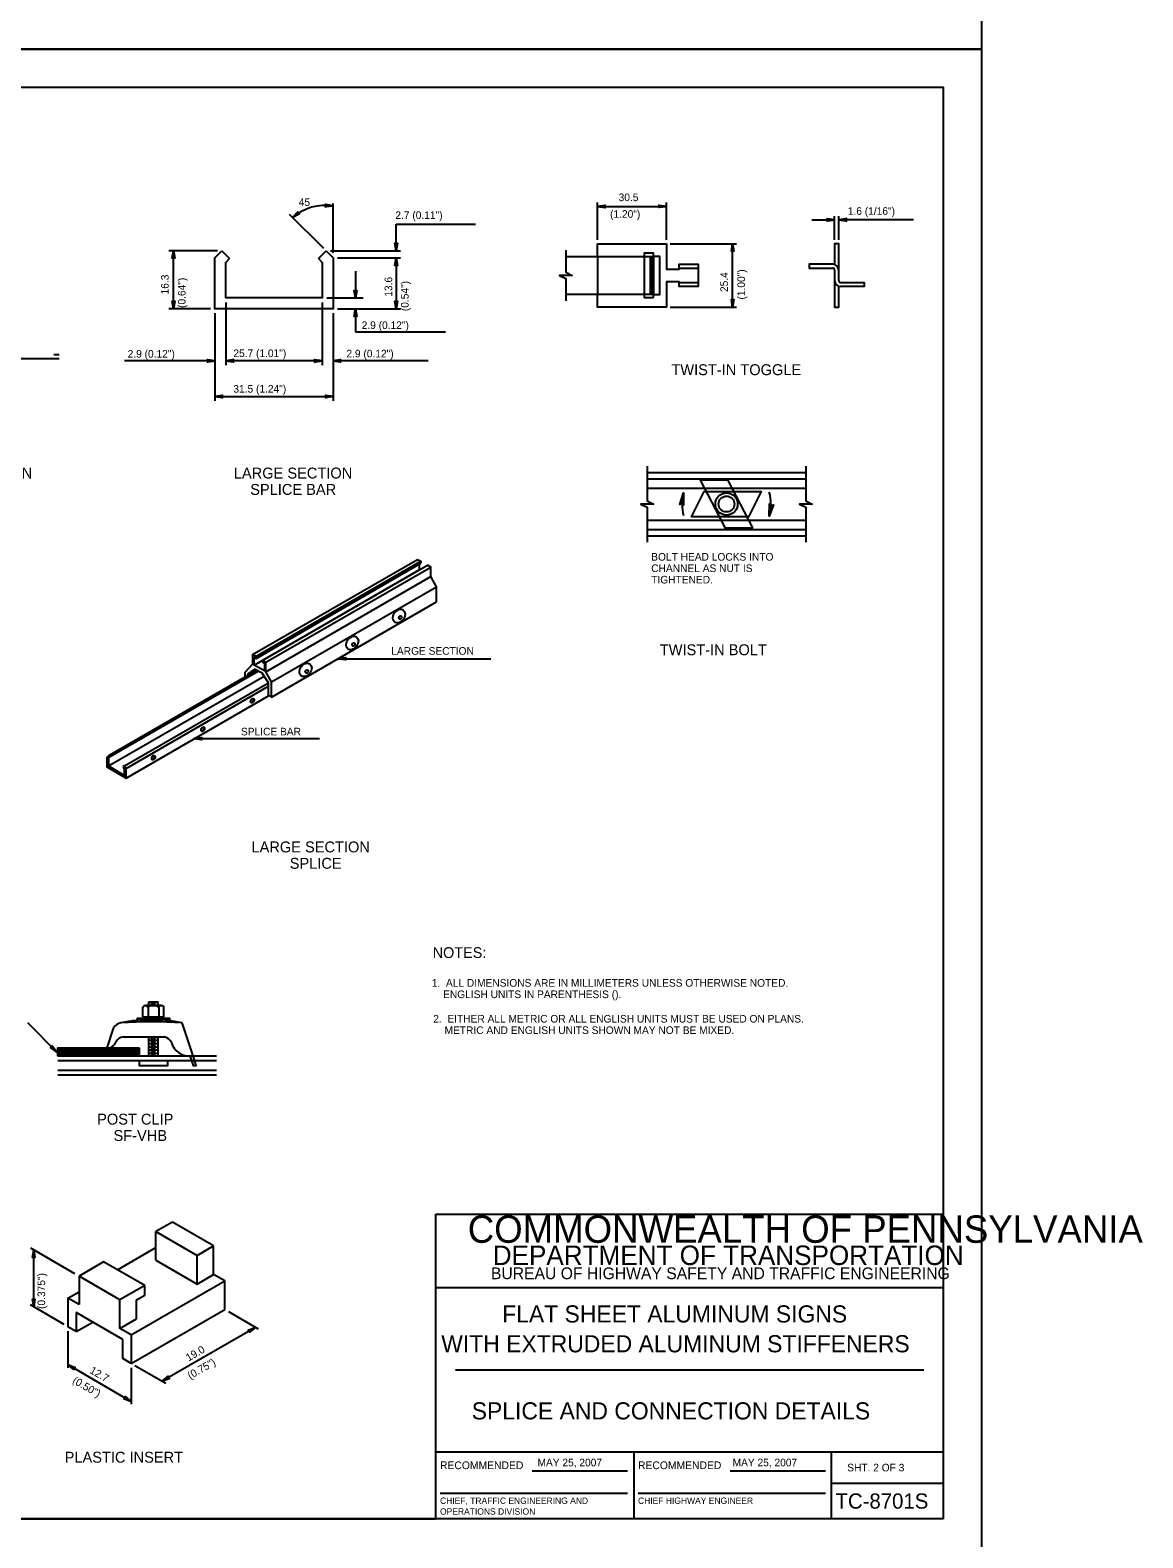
# Model space of a CAD drawing. Extents: x 650495 to 651400, y 297864 to 299646.
# Drawn here: x 650962 to 651400, y 298465 to 299059 of the extents above; entities that cross this region are included whole.
import ezdxf

# ---------------------------------------------------------------- set-up
doc = ezdxf.new("R2010")
doc.units = 0
for name, color, linetype in [('1', 7, 'Continuous'), ('2', 7, 'Continuous'), ('3', 7, 'Continuous'), ('PLT-BNDY', 7, 'Continuous')]:
    doc.layers.add(name, color=color, linetype=linetype)

# ---------------------------------------------------------------- blocks, each defined once
blk = doc.blocks.new('RARROW')
at = {"layer": '3'}
blk.add_lwpolyline([(-2.2695, 0.285), (-2.184875, 0.12075), (0, 0), (-2.2695, 0.285), (-2.38575, 0.384625), (0, 0), (-2.183125, -0.108), (-2.262875, -0.2705), (0, 0), (-2.38575, -0.379125), (-2.262875, -0.2705)], dxfattribs=at)

msp = doc.modelspace()

# ---------------------------------------------------------------- linework, layer by layer
at = {"layer": '1'}
for p, q in [((650535.31, 299036.63), (651321.31, 299036.63)), ((651321.31, 298472.63), (651321.31, 299036.63)), ((651121.31, 298472.63), (651121.31, 298592.63)), ((651121.31, 298592.63), (651321.31, 298592.63)), ((651321.31, 298563.63), (651121.31, 298563.63)), ((651129.06, 298531.31), (651313.56, 298531.31)), ((651121.31, 298499), (651321.31, 298499)), ((651199.31, 298499), (651199.31, 298472.63)), ((651277.19, 298472.63), (651277.19, 298499)), ((651159.24, 298491.57), (651196.87, 298491.57)), ((651237.24, 298491.57), (651274.87, 298491.57)), ((651277.19, 298486.63), (651321.31, 298486.63)), ((651122.99, 298482.68), (651196.87, 298482.68)), ((651200.99, 298482.68), (651274.87, 298482.68)), ((651321.31, 298472.63), (650535.31, 298472.63)), ((650535.31, 298472.63), (651121.31, 298472.63))]:
    msp.add_line(p, q, dxfattribs=at)
at = {"layer": '2'}
for p, q in [((651080.83, 298971.36), (651080.83, 298990.86)), ((651185.07, 298976.5), (651185.07, 298991.19)), ((651212.14, 298976.5), (651212.14, 298991.19)), ((651077.21, 298973.11), (651063.71, 298986.49)), ((651185.07, 298989.69), (651212.14, 298989.69)), ((651269.44, 298984.38), (651278.44, 298984.38)), ((651278.44, 298976.5), (651278.44, 298985.88)), ((651280.06, 298976.5), (651280.06, 298985.88)), ((651309.47, 298984.38), (651280.06, 298984.38)), ((651105.71, 298972.23), (651105.71, 298982.74)), ((651105.71, 298982.74), (651136.92, 298982.74)), ((651035.33, 298972.23), (651016.21, 298972.23)), ((651017.96, 298949.36), (651017.96, 298972.23)), ((651037.08, 298972.23), (651040.08, 298969.11)), ((651075.08, 298969.11), (651078.08, 298972.23)), ((651079.83, 298972.23), (651107.46, 298972.23)), ((651213.64, 298975), (651239.76, 298975)), ((651238.26, 298950), (651238.26, 298975)), ((651082.58, 298969.36), (651107.46, 298969.36)), ((651105.71, 298969.36), (651105.71, 298949.36)), ((651185.07, 298970), (651185.07, 298955)), ((651203.39, 298970), (651203.39, 298955)), ((651205.76, 298970), (651205.76, 298955)), ((651206.51, 298970), (651206.51, 298955)), ((651089.65, 298964.11), (651089.65, 298953.61)), ((651217.14, 298965.38), (651224.64, 298965.38)), ((651278.44, 298964.63), (651278.44, 298960.5)), ((651217.14, 298959.75), (651224.64, 298959.75)), ((651032.58, 298949.36), (651016.21, 298949.36)), ((651038.58, 298951.86), (651038.58, 298927.09)), ((651076.58, 298951.86), (651076.58, 298927.09)), ((651078.33, 298953.61), (651092.72, 298953.61)), ((651082.58, 298949.36), (651096.83, 298949.36)), ((651082.58, 298949.36), (651107.46, 298949.36)), ((651089.65, 298949.36), (651089.65, 298940.23)), ((651213.64, 298950), (651239.76, 298950)), ((651034.33, 298947.61), (651034.33, 298927.09)), ((651034.33, 298947.61), (651034.33, 298913.08)), ((651080.83, 298947.61), (651080.83, 298927.09)), ((651080.83, 298947.61), (651080.83, 298913.08)), ((651089.65, 298940.23), (651125.18, 298940.23)), ((650970.9, 298931.39), (650972.89, 298931.39)), ((650888.65, 298929.7), (650973, 298929.7)), ((651034.33, 298928.84), (650998.63, 298928.84)), ((651076.58, 298928.84), (651038.58, 298928.84)), ((651087.08, 298928.84), (651080.83, 298928.84)), ((651118.32, 298928.84), (651080.83, 298928.84)), ((651034.33, 298914.83), (651080.83, 298914.83)), ((651204.56, 298884.88), (651267.06, 298884.88)), ((651204.56, 298882.38), (651267.06, 298882.38)), ((651204.56, 298878.63), (651267.06, 298878.63)), ((651204.56, 298866.13), (651267.06, 298866.13)), ((651204.56, 298862.38), (651267.06, 298862.38)), ((651204.56, 298859.88), (651267.06, 298859.88)), ((651049.15, 298813.11), (651114.15, 298850.61)), ((651049.78, 298811.99), (651114.78, 298849.49)), ((651050.53, 298812.36), (651115.4, 298849.86)), ((651050.53, 298811.61), (651115.4, 298849.11)), ((651053.15, 298810.86), (651118.03, 298848.36)), ((651054.4, 298810.11), (651119.4, 298847.61)), ((651049.78, 298808.99), (651114.78, 298846.49)), ((651054.4, 298806.36), (651119.4, 298843.86)), ((651056.65, 298802.36), (651121.65, 298839.86)), ((651056.65, 298796.36), (651121.65, 298833.86)), ((650992.65, 298773.49), (651050.65, 298806.99)), ((650993.03, 298772.99), (651051.28, 298806.61)), ((651082.9, 298811.49), (651142.95, 298811.49)), ((650992.4, 298769.24), (651053.65, 298804.61)), ((650998.65, 298769.24), (651055.4, 298801.99)), ((650999.28, 298768.24), (651055.4, 298800.61)), ((650999.28, 298764.49), (651055.4, 298796.86)), ((651026.15, 298779.99), (651075.57, 298779.99)), ((650993.03, 298772.99), (650992.65, 298773.49)), ((650998.65, 298769.24), (650998.15, 298768.99)), ((651008.22, 298676.27), (651011.97, 298676.27)), ((651008.22, 298674.89), (651008.22, 298676.27)), ((651008.35, 298676.14), (651011.72, 298676.14)), ((651009.1, 298675.52), (651010.85, 298675.52)), ((651011.97, 298674.89), (651011.97, 298676.27)), ((651005.85, 298670.39), (651005.85, 298674.14)), ((651005.85, 298670.39), (651014.22, 298670.39)), ((651006.22, 298670.39), (651006.22, 298670.14)), ((651006.22, 298670.14), (651013.97, 298670.14)), ((651013.1, 298674.89), (651006.97, 298674.89)), ((651007.97, 298674.02), (651007.97, 298670.39)), ((651012.22, 298674.02), (651012.22, 298670.39)), ((651013.97, 298670.39), (651013.97, 298670.14)), ((651014.22, 298670.39), (651014.22, 298674.14)), ((650971.97, 298656.52), (650960.54, 298668.02)), ((650991.85, 298658.14), (650994.47, 298666.14)), ((651025.72, 298655.02), (651021.35, 298668.02)), ((650998.22, 298662.52), (651014.47, 298662.52)), ((651008.22, 298655.02), (651008.22, 298662.52)), ((651008.35, 298662.39), (651011.72, 298662.39)), ((651008.35, 298661.14), (651011.72, 298661.14)), ((651008.35, 298659.89), (651011.72, 298659.89)), ((651008.35, 298658.64), (651011.72, 298658.64)), ((651008.35, 298657.39), (651011.72, 298657.39)), ((651009.1, 298661.77), (651010.85, 298661.77)), ((651009.1, 298660.52), (651010.85, 298660.52)), ((651009.1, 298659.27), (651010.85, 298659.27)), ((651009.1, 298658.02), (651010.85, 298658.02)), ((651011.97, 298655.02), (651011.97, 298662.52)), ((650972.47, 298655.02), (651034.97, 298655.02)), ((650972.47, 298653.14), (651034.97, 298653.14)), ((651008.35, 298656.14), (651011.72, 298656.14)), ((651009.1, 298656.77), (651010.85, 298656.77)), ((651009.1, 298655.52), (651010.85, 298655.52)), ((651015.72, 298653.14), (651015.72, 298653.14)), ((651024.47, 298655.02), (651024.47, 298655.02)), ((650972.47, 298649.39), (651034.97, 298649.39)), ((650972.47, 298647.52), (651034.97, 298647.52)), ((651017.53, 298589.51), (651011.03, 298585.76)), ((651033.78, 298580.13), (651017.53, 298589.51)), ((651011.03, 298585.76), (651027.28, 298576.38)), ((651011.03, 298574.51), (651011.03, 298585.76)), ((651027.28, 298576.38), (651033.78, 298580.13)), ((651033.78, 298568.88), (651033.78, 298580.13)), ((650979.16, 298569.13), (650961.78, 298579.28)), ((650962.91, 298556.13), (650962.91, 298578.63)), ((650995.91, 298570.76), (651011.03, 298579.51)), ((651011.03, 298574.51), (651027.28, 298565.13)), ((651027.28, 298565.13), (651027.28, 298576.38)), ((650990.41, 298573.88), (650980.78, 298568.26)), ((650996.91, 298558.88), (650980.78, 298568.26)), ((650980.78, 298568.26), (650980.78, 298557.01)), ((651006.66, 298564.51), (650990.41, 298573.88)), ((651027.28, 298565.13), (651033.78, 298568.88)), ((651038.16, 298566.38), (651033.78, 298568.88)), ((651006.66, 298564.51), (650996.91, 298558.88)), ((651001.28, 298545.13), (651038.16, 298566.38)), ((651006.66, 298560.76), (651006.66, 298564.51)), ((651038.16, 298555.13), (651038.16, 298566.38)), ((650974.91, 298549.13), (650961.59, 298556.9)), ((650976.41, 298559.51), (650980.78, 298562.01)), ((650976.41, 298559.51), (650976.41, 298548.26)), ((650980.78, 298557.01), (650976.41, 298559.51)), ((650996.91, 298547.63), (650996.91, 298558.88)), ((651003.41, 298558.88), (651006.66, 298560.76)), ((651003.41, 298551.38), (651003.41, 298558.88)), ((650998.03, 298543.26), (650979.66, 298553.88)), ((650979.66, 298553.88), (650979.66, 298546.38)), ((650996.91, 298547.63), (651003.41, 298551.38)), ((651001.28, 298533.88), (651038.16, 298555.13)), ((651039.66, 298554.26), (651051.28, 298547.49)), ((650979.66, 298546.38), (650976.41, 298548.26)), ((650976.41, 298546.51), (650976.41, 298532.13)), ((650979.66, 298546.38), (650986.16, 298550.13)), ((651001.28, 298545.13), (650996.91, 298547.63)), ((651001.28, 298545.13), (651001.28, 298533.88)), ((651050.3, 298548.06), (651013.58, 298526.84)), ((650998.03, 298535.76), (650998.03, 298543.26)), ((650976.41, 298533.36), (651001.28, 298518.84)), ((651001.28, 298533.88), (650998.03, 298535.76)), ((651002.78, 298533.01), (651014.99, 298526.03)), ((651001.28, 298532.13), (651001.28, 298517.76))]:
    msp.add_line(p, q, dxfattribs=at)
for points in [[(651078.08, 298972.23), (651080.83, 298969.36), (651080.83, 298949.36), (651034.33, 298949.36), (651034.33, 298969.36), (651037.08, 298972.23)], [(651172.57, 298972.5), (651172.57, 298963.75), (651175.07, 298962.5), (651170.07, 298962.5), (651172.57, 298961.25), (651172.57, 298952.5)], [(651185.07, 298970), (651185.07, 298975), (651212.14, 298975), (651212.14, 298965), (651217.14, 298965), (651217.14, 298966.88), (651224.64, 298966.88), (651224.64, 298958.13), (651217.14, 298958.13), (651217.14, 298960), (651212.14, 298960), (651212.14, 298950), (651185.07, 298950), (651185.07, 298955)], [(651280.06, 298960.5), (651280.06, 298975), (651278.44, 298975), (651278.44, 298966.78)], [(651075.08, 298969.11), (651076.58, 298967.61), (651076.58, 298953.61), (651038.58, 298953.61), (651038.58, 298967.61), (651040.08, 298969.11)], [(651172.57, 298970), (651207.14, 298970), (651207.14, 298955), (651172.57, 298955)], [(651277.76, 298966.88), (651268.44, 298966.88), (651268.44, 298965.38), (651277.69, 298965.38)], [(651278.44, 298964.63), (651278.44, 298950), (651280.06, 298950), (651280.06, 298958.23)], [(651280.81, 298959.75), (651290.06, 298959.75), (651290.06, 298958.13), (651280.74, 298958.13)], [(651204.56, 298887.38), (651204.56, 298873.63), (651207.06, 298872.38), (651202.06, 298872.38), (651204.56, 298871.13), (651204.56, 298857.38)], [(651267.06, 298887.38), (651267.06, 298873.63), (651269.56, 298872.38), (651264.56, 298872.38), (651267.06, 298871.13), (651267.06, 298857.38)], [(651235.81, 298877.38), (651249.56, 298877.38), (651244.56, 298867.38), (651222.06, 298867.38), (651227.06, 298877.38), (651235.81, 298877.38)], [(651231.69, 298870.25), (651225.56, 298881.88), (651236.19, 298882), (651246.06, 298863), (651235.44, 298862.88), (651231.69, 298870.25)], [(651217.69, 298872.5), (651217.94, 298872.63), (651218.94, 298876.88), (651217.69, 298872.5), (651217.44, 298872.25), (651218.94, 298876.88), (651218.44, 298872.5), (651218.69, 298872.38), (651218.94, 298876.88), (651218.94, 298872), (651218.69, 298872.38)], [(651254.06, 298872), (651253.69, 298871.88), (651252.69, 298867.63), (651254.06, 298872), (651254.31, 298872.13), (651252.69, 298867.63), (651253.19, 298872), (651252.94, 298872.13), (651252.69, 298867.63), (651252.81, 298872.5), (651252.94, 298872.13)], [(651114.15, 298850.61), (651115.4, 298849.86), (651115.4, 298849.11)], [(651114.78, 298848.74), (651114.78, 298846.49)], [(651121.65, 298833.86), (651121.65, 298839.86), (651119.4, 298843.86), (651119.4, 298847.61), (651118.03, 298848.36)], [(651055.4, 298797.11), (651056.65, 298796.36), (651056.65, 298802.36), (651054.4, 298806.36), (651054.4, 298810.11), (651053.15, 298810.86), (651053.15, 298810.11), (651053.78, 298809.74), (651053.78, 298806.74), (651049.78, 298808.99), (651049.78, 298811.99), (651050.53, 298811.61), (651050.53, 298812.36), (651049.15, 298813.11), (651049.15, 298809.36), (651046.03, 298806.11), (651046.03, 298804.24)], [(651055.4, 298797.11), (651055.4, 298801.99), (651052.9, 298805.74), (651049.9, 298807.36), (651047.28, 298805.49), (651047.28, 298804.99)], [(650992.65, 298773.49), (650991.78, 298772.61), (650991.78, 298768.86), (650999.28, 298764.49), (650999.28, 298768.24), (650998.65, 298769.24)], [(650993.03, 298772.99), (650992.4, 298772.36), (650992.4, 298769.24), (650998.65, 298765.49), (650998.65, 298767.99), (650998.15, 298768.99)], [(650972.72, 298657.52), (651003.97, 298657.52), (651003.97, 298655.64), (650972.72, 298655.39), (650972.72, 298657.14), (651003.47, 298657.14), (651003.6, 298656.14), (650973.35, 298655.64), (650973.47, 298656.64), (651002.72, 298656.64), (651002.72, 298656.52), (650973.6, 298656.14)], [(651004.47, 298653.14), (651004.47, 298651.27), (651015.72, 298651.27), (651015.72, 298653.14)], [(651024.47, 298655.02), (651025.72, 298651.27), (651026.97, 298651.27), (651025.72, 298655.02)]]:
    msp.add_lwpolyline(points, dxfattribs=at)
for points in [[(651207.14, 298970), (651207.14, 298971.25), (651203.39, 298971.25), (651203.39, 298970)], [(651207.14, 298970), (651207.14, 298955), (651209.64, 298955), (651209.64, 298970)], [(651207.14, 298953.75), (651207.14, 298955), (651203.39, 298955), (651203.39, 298953.75)], [(651003.85, 298669.27), (651003.85, 298669.89), (651016.35, 298669.89), (651016.35, 298669.27)], [(651004.47, 298658.14), (651004.47, 298655.02), (650972.47, 298655.02), (650972.47, 298658.14)]]:
    msp.add_lwpolyline(points, close=True, dxfattribs=at)
for radius in [4.38, 3.12]:
    msp.add_circle((651235.85, 298872.42), radius, dxfattribs=at)
for centre, radius, start, end in [((651077.83, 298969.94), 20.14, 81.42065, 130.10106), ((651277.76, 298964.58), 2.3, 0, 90), ((651277.69, 298964.63), 0.75, 0, 90), ((651280.74, 298960.43), 2.3, 180, 270), ((651280.81, 298960.5), 0.75, 180, 270), ((651235.85, 298872.42), 17.49, 344.07384, 15.48813), ((651235.85, 298872.42), 17.49, 165.2574, 194.94011), ((651009.31, 298612.21), 57.12, 77.80349, 102.1965), ((651007.03, 298674.76), 0.113, 90, 180), ((651013.1, 298674.76), 0.113, 0, 90), ((650998.31, 298663.56), 4.6, 103.47229, 145.70272), ((651009.31, 298493.5), 174.95, 86.04462, 93.95539), ((650991.89, 298661.49), 3.48, 282.55259, 342.47234), ((650998.61, 298658.69), 3.82, 95.78592, 152.80494), ((651013.51, 298658.45), 4.15, 26.88629, 76.60858), ((651024.12, 298662.12), 7.13, 194.52183, 272.8108)]:
    msp.add_arc(centre, radius, start, end, dxfattribs=at)
for centre, major_axis, ratio in [((651106.81, 298828.32), (1.7, 2.34), 0.738176), ((651107.29, 298827.73), (0.425, 0.585), 0.738176), ((651088.41, 298817.69), (1.7, 2.34), 0.738176), ((651088.89, 298817.11), (0.425, 0.585), 0.738176), ((651070, 298807.07), (1.7, 2.34), 0.738176), ((651070.48, 298806.48), (0.425, 0.585), 0.738176), ((651049.05, 298795.01), (0.443, 0.822), 0.636755), ((651029.56, 298783.76), (0.443, 0.822), 0.636755), ((651010.07, 298772.51), (0.443, 0.822), 0.636755)]:
    msp.add_ellipse(centre, major_axis=major_axis, ratio=ratio, dxfattribs=at)
for centre, major_axis, ratio, start_param, end_param in [((651048.88, 298795.1), (0.443, 0.822), 0.636755, 3.280378, 6.105665), ((651029.4, 298783.85), (0.443, 0.822), 0.636755, 3.280378, 6.105665), ((651009.91, 298772.6), (0.443, 0.822), 0.636755, 3.280378, 6.105665), ((651006.91, 298674.04), (1.03, 0.01), 0.679853, 0, 3.035161), ((651010.06, 298674.06), (-2.12, -0.01), 0.335964, 3.141593, 6.283185), ((651013.21, 298674.06), (-1.03, 0.01), 0.679853, 3.248025, 6.283185)]:
    msp.add_ellipse(centre, major_axis=major_axis, ratio=ratio, start_param=start_param, end_param=end_param, dxfattribs=at)
at = {"layer": 'PLT-BNDY'}
for points in [[(650495.31, 299645.63), (651336.31, 299645.63), (651336.31, 299051.63), (650495.31, 299051.63)], [(650495.31, 299051.63), (651336.31, 299051.63), (651336.31, 298457.63), (650495.31, 298457.63)]]:
    msp.add_lwpolyline(points, close=True, dxfattribs=at)

# ---------------------------------------------------------------- block references
at = {"layer": '2'}
for p, xscale, yscale, rotation in [((651080.83, 298989.86), 1.257434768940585, 1.3092961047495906, -4.1307990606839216), ((651185.07, 298989.69), 1.2574347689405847, 1.3092961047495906, 180), ((651064.86, 298985.35), 1.2574347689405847, 1.3092961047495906, -143.18293648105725), ((651280.06, 298984.38), 1.2574347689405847, 1.3092961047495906, 180), ((651017.96, 298972.23), 1.2574347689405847, 1.3092961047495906, 89.99999999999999), ((651105.71, 298972.23), 1.2574347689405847, 1.3092961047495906, -90.00000000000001), ((651238.26, 298975), 1.2574347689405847, 1.3092961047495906, 89.99999999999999), ((651105.71, 298969.36), 1.2574347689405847, 1.3092961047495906, 89.99999999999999), ((651089.65, 298953.61), 1.2574347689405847, 1.3092961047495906, -90.00000000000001), ((651017.96, 298949.36), 1.2574347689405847, 1.3092961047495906, -90.00000000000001), ((651089.65, 298949.36), 1.2574347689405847, 1.3092961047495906, 89.99999999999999), ((651105.71, 298949.36), 1.2574347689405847, 1.3092961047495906, -90.00000000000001), ((651238.26, 298950), 1.2574347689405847, 1.3092961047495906, -90.00000000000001), ((651038.58, 298928.84), 1.2574347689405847, 1.3092961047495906, 180), ((651080.83, 298928.84), 1.2574347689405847, 1.3092961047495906, 180), ((651034.33, 298914.83), 1.2574347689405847, 1.3092961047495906, 180), ((651082.9, 298811.49), 1.2574347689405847, 1.3092961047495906, 180), ((651026.15, 298779.99), 1.2574347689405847, 1.3092961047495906, 180), ((650971.97, 298656.52), 1.2574347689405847, 1.3092961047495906, -44.8426609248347), ((650971.97, 298656.52), 0.0018861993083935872, 0.001963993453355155, -46.50743575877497), ((650962.91, 298578.63), 1.2574347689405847, 1.3092961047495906, 89.99999999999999), ((650962.91, 298556.13), 1.2574347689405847, 1.3092961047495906, -90.00000000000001), ((651050.3, 298548.06), 1.2574347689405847, 1.3092961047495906, 30.434578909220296), ((650976.41, 298533.35), 1.2574347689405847, 1.3092961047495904, 149.64469446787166), ((651013.58, 298526.84), 1.2574347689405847, 1.3092961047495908, -149.86157797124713), ((651001.28, 298518.84), 1.2574347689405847, 1.3092961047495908, -30.0868603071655)]:
    msp.add_blockref('RARROW', p, dxfattribs=dict(at, xscale=xscale, yscale=yscale, rotation=rotation))
at = {"layer": '2', "xscale": 1.2574347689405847, "yscale": 1.3092961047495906}
for p in [(651212.14, 298989.69), (651278.44, 298984.38), (651034.33, 298928.84), (651076.58, 298928.84), (651080.83, 298914.83)]:
    msp.add_blockref('RARROW', p, dxfattribs=at)

# ---------------------------------------------------------------- texts
at = {"layer": '1'}
for s, height, p in [('COMMONWEALTH OF PENNSYLVANIA', 10.7828, (651133.9, 298581.36)), ('DEPARTMENT OF TRANSPORTATION', 7.6837, (651143.76, 298572.61)), ('BUREAU OF HIGHWAY SAFETY AND TRAFFIC ENGINEERING', 4.6253, (651143.04, 298567.04)), ('FLAT SHEET ALUMINUM SIGNS', 6.75, (651147.47, 298549.97)), ('WITH EXTRUDED ALUMINUM STIFFENERS', 6.75, (651123.47, 298538.22)), ('SPLICE AND CONNECTION DETAILS', 6.75, (651135.47, 298511.78)), ('RECOMMENDED', 3.048, (651122.99, 298492.2)), ('RECOMMENDED', 3.048, (651200.99, 298492.2)), ('SHT. 2 OF 3', 3, (651283.4, 298491.31)), ('CHIEF, TRAFFIC ENGINEERING AND', 2.5, (651122.99, 298478.51)), ('CHIEF HIGHWAY ENGINEER', 2.5, (651200.99, 298478.51)), ('TC-8701S', 6, (651278.79, 298476.63)), ('OPERATIONS DIVISION', 2.5, (651122.99, 298474.26))]:
    msp.add_text(s, height=height, dxfattribs=at).set_placement(p)
at = {"layer": '2'}
for s, height, p in [('45', 2.999, (651067.33, 298989.86)), ('30.5', 3, (651193.34, 298991.76)), ('2.7 (0.11")', 3, (651105.39, 298984.74)), ('(1.20")', 3, (651189.98, 298985.2)), ('1.6 (1/16")', 3, (651283.63, 298986.37)), ('2.9 (0.12")', 3, (651092.12, 298941.39)), ('2.9 (0.12")', 3, (650999.92, 298930.1)), ('25.7 (1.01")', 3, (651041.58, 298930.34)), ('2.9 (0.12")', 3, (651086.12, 298930.2)), ('TWIST-IN TOGGLE', 4.3, (651214.15, 298923.2)), ('31.5 (1.24")', 3, (651041.57, 298916.32)), ('SINGLE LARGE SECTION', 4.3, (650892.99, 298882.48)), ('LARGE SECTION', 4.3, (651041.76, 298882.48)), ('SPLICE BAR', 4.3, (651048.21, 298876.03)), ('CHANNEL AS NUT IS', 3, (651206.19, 298845.63)), ('BOLT HEAD LOCKS INTO', 3, (651206.19, 298850.13)), ('TIGHTENED.', 3, (651206.19, 298841.13)), ('LARGE SECTION', 3, (651103.77, 298813.05)), ('TWIST-IN BOLT', 4.3, (651209.57, 298812.86)), ('SPLICE BAR', 3, (651044.57, 298781.27)), ('LARGE SECTION', 4.3, (651048.71, 298735.18)), ('SPLICE', 4.3, (651063.78, 298728.73)), ('NOTES:', 4.25, (651120.08, 298693.58)), ('1.  ALL DIMENSIONS ARE IN MILLIMETERS UNLESS OTHERWISE NOTED.', 3, (651119.74, 298682.27)), ('    ENGLISH UNITS IN PARENTHESIS ().', 3, (651119.74, 298677.77)), ('2.  EITHER ALL METRIC OR ALL ENGLISH UNITS MUST BE USED ON PLANS.', 3, (651120.31, 298668.13)), ('    METRIC AND ENGLISH UNITS SHOWN MAY NOT BE MIXED.', 3, (651120.31, 298663.63)), ('POST CLIP', 4.3, (650987.91, 298627.94)), ('SF-VHB', 4.3, (650994.36, 298621.49)), ('PLASTIC INSERT', 4.3, (650975.11, 298494.74)), ('MAY 25, 2007', 3, (651161.39, 298493.31)), ('MAY 25, 2007', 3, (651238.25, 298493.31))]:
    msp.add_text(s, height=height, dxfattribs=at).set_placement(p)
for s, rotation, p in [('16.3', 90, (651016.08, 298955.01)), (' (0.64")', 90, (651022.73, 298948.57)), ('13.6', 90, (651104.15, 298954.11)), ('25.4 ', 90, (651236.41, 298955.95)), ('(1.00")', 90, (651243.14, 298953)), (' (0.54")', 90, (651110.61, 298947.3)), ('(0.375")', 90, (650967.42, 298555.32)), ('19.0', 30.02706, (651023.91, 298534.54)), ('(0.75")', 30.02706, (651024.59, 298527.5)), ('(0.50")', 329.74364, (650977.9, 298526.32)), ('12.7', 329.74364, (650984.69, 298530.26))]:
    msp.add_text(s, height=3, rotation=rotation, dxfattribs=at).set_placement(p)

doc.saveas('drawing.dxf')
